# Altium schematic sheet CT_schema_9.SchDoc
size 308 x 210 mm
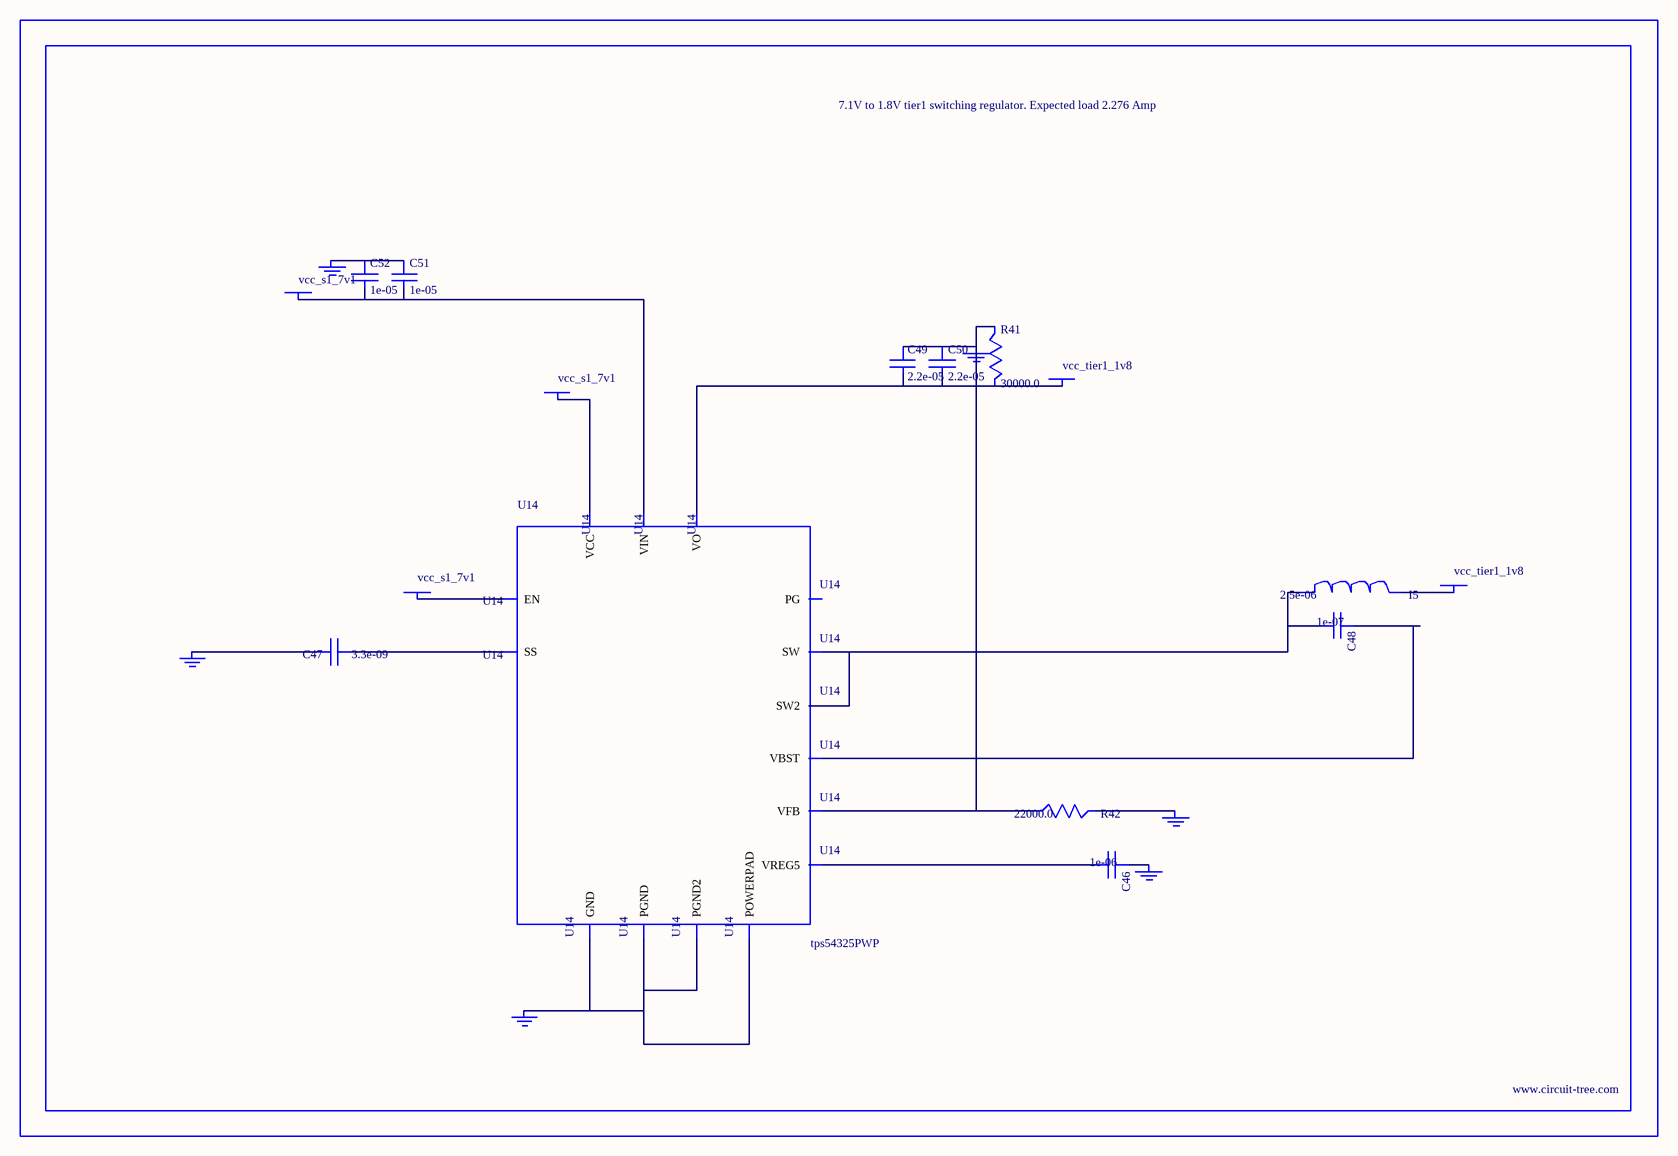
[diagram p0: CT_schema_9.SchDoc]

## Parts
BORDER8  (no value)
C46  1e-06  [C0603]
C47  3.3e-09  [C0402]
C48  1e-07  [C0402]
C49  2.2e-05  [C1210]
C50  2.2e-05  [C1210]
C51  1e-05  [C1206]
C52  1e-05  [C1206]
GND_INSTANCE_8_0  (no value)
GND_INSTANCE_8_1  (no value)
GND_INSTANCE_8_2  (no value)
GND_INSTANCE_8_3  (no value)
GND_INSTANCE_8_4  (no value)
GND_INSTANCE_8_5  (no value)
I5  2.5e-06  [DR1040]
POWER_INSTANCE_8_0  vcc_tier1_1v8
POWER_INSTANCE_8_1  vcc_s1_7v1
POWER_INSTANCE_8_2  vcc_tier1_1v8
POWER_INSTANCE_8_3  vcc_s1_7v1
POWER_INSTANCE_8_4  vcc_s1_7v1
R41  30000.0  [R0603]
R42  22000.0  [R0603]
U14  tps54325PWP  [HTSSOP14]

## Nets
NetC46_1: C46.1 GND_INSTANCE_8_2.0(GND)
NetC46_2: C46.2 U14.3(VREG5)
NetC47_1: C47.1 U14.4(SS)
NetC47_2: C47.2 GND_INSTANCE_8_3.0(GND)
NetC48_1: C48.1 U14.12(VBST)
NetC48_2: C48.2 I5.1 U14.10(SW) U14.11(SW2)
NetC49_1: C49.1 C50.1 GND_INSTANCE_8_0.0(GND) R41.1 R42.1 U14.2(VFB)
NetC49_2: C49.2 C50.2 POWER_INSTANCE_8_0.0(PWR) R41.2 U14.1(VO)
NetC51_1: C51.1 C52.1 GND_INSTANCE_8_5.0(GND)
NetC51_2: C51.2 C52.2 POWER_INSTANCE_8_3.0(PWR) U14.13(VIN)
NetGND_INSTANCE_8_1_0: GND_INSTANCE_8_1.0(GND) R42.2
NetGND_INSTANCE_8_4_0: GND_INSTANCE_8_4.0(GND) U14.5(GND) U14.8(PGND) U14.9(PGND2) U14.15(POWERPAD)
NetI5_2: I5.2 POWER_INSTANCE_8_2.0(PWR)
NetPOWER_INSTANCE_8_1_0: POWER_INSTANCE_8_1.0(PWR) U14.7(EN)
NetPOWER_INSTANCE_8_4_0: POWER_INSTANCE_8_4.0(PWR) U14.14(VCC)

Not connected (* = marked no-connect by the designer): U14 6(PG)

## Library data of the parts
BORDER8 = BORDER_PAGE8
C46 = C0603C105K3RACTU
C47 = C0402C332K3RAC
C48 = C0402C104K3RACTU
C49 C50 = GRM32ER61E226ME15L
C51 C52 = C1206C106K3RACTU
GND_INSTANCE_8_0-GND_INSTANCE_8_5 = GND
I5 = DR1040-2R5-R
POWER_INSTANCE_8_0-POWER_INSTANCE_8_4 = PWR
R41 = RC0603JR-0730KL
R42 = RC0603JR-0722KL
